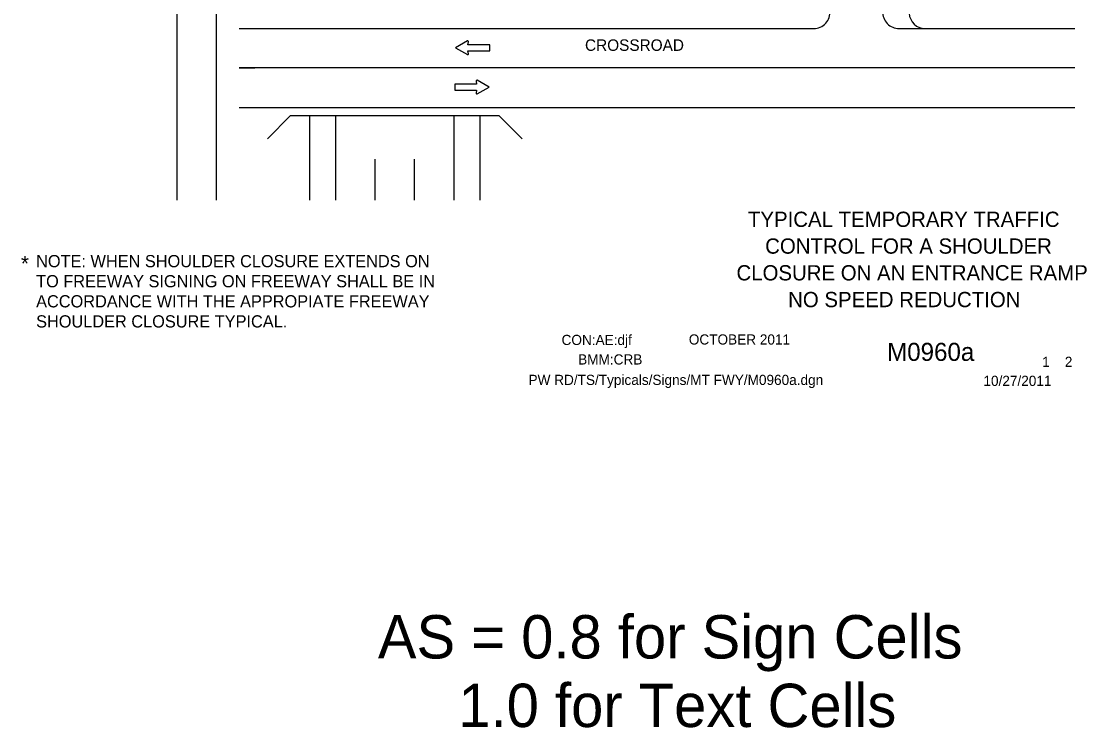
# Model space of a CAD drawing. Extents: x 16733 to 18471, y 4586 to 5876.
# Drawn here: x 16761 to 17411, y 4586 to 5017 of the extents above; entities that cross this region are included whole.
import ezdxf

# ---------------------------------------------------------------- set-up
doc = ezdxf.new("R2010")
doc.units = 0
for name, color, linetype in [('BORDER', 7, 'Continuous'), ('BORDER_SIGNAL_WO', 7, 'Continuous'), ('MT_SCRATCH_LEVEL_E', 7, 'Continuous'), ('PAVT_EDGE_EX', 7, 'Continuous'), ('TRAFFIC_SIGNS_PR', 7, 'Continuous')]:
    doc.layers.add(name, color=color, linetype=linetype)

msp = doc.modelspace()

# ---------------------------------------------------------------- linework, layer by layer
at = {"layer": 'MT_SCRATCH_LEVEL_E'}
for p, q in [((17033.24, 5004.69), (17026, 5000.54)), ((17033.24, 5004.69), (17026, 5000.54)), ((17033.61, 5002.43), (17033.92, 5004.21)), ((17033.61, 5002.43), (17033.92, 5004.21)), ((17046.86, 5002.43), (17033.61, 5002.43)), ((17046.86, 5002.43), (17033.61, 5002.43)), ((17046.86, 4998.69), (17046.86, 5002.43)), ((17046.86, 4998.69), (17046.86, 5002.43)), ((17026, 5000.54), (17033.24, 4996.43)), ((17026, 5000.54), (17033.24, 4996.43)), ((17033.92, 4996.91), (17033.61, 4998.69)), ((17033.61, 4998.69), (17046.86, 4998.69)), ((17033.92, 4996.91), (17033.61, 4998.69)), ((17033.61, 4998.69), (17046.86, 4998.69)), ((17038.89, 4978.47), (17025.63, 4978.47)), ((17025.63, 4978.47), (17025.63, 4974.73)), ((17038.89, 4978.47), (17025.63, 4978.47)), ((17025.63, 4978.47), (17025.63, 4974.73)), ((17038.57, 4980.25), (17038.89, 4978.47)), ((17038.57, 4980.25), (17038.89, 4978.47)), ((17046.5, 4976.62), (17039.26, 4980.73)), ((17046.5, 4976.62), (17039.26, 4980.73)), ((17039.26, 4972.47), (17046.5, 4976.62)), ((17039.26, 4972.47), (17046.5, 4976.62)), ((17025.63, 4974.73), (17038.89, 4974.73)), ((17025.63, 4974.73), (17038.89, 4974.73)), ((17038.89, 4974.73), (17038.57, 4972.95)), ((17038.89, 4974.73), (17038.57, 4972.95))]:
    msp.add_line(p, q, dxfattribs=at)
for centre, start, end in [((17033.46, 5004.28), 350.03619, 119.77312), ((17033.46, 5004.28), 350.03619, 119.77312), ((17033.46, 4996.84), 240.42484, 9.96381), ((17033.46, 4996.84), 240.42484, 9.96381), ((17039.03, 4980.32), 60.42484, 189.96381), ((17039.03, 4980.32), 60.42484, 189.96381), ((17039.03, 4972.88), 170.03619, 299.77312), ((17039.03, 4972.88), 170.03619, 299.77312)]:
    msp.add_arc(centre, 0.463, start, end, dxfattribs=at)
at = {"layer": 'PAVT_EDGE_EX'}
for p, q in [((16894.1, 5012.24), (17244.4, 5012.24)), ((17296.56, 5012.24), (17403.74, 5012.24)), ((16894.1, 4964.24), (17403.74, 4964.24)), ((16925.44, 4959.24), (16911.3, 4945.09)), ((16925.44, 4959.24), (17052.44, 4959.24)), ((16936.94, 4959.24), (16936.94, 4907.7)), ((16952.94, 4959.24), (16952.94, 4907.7)), ((17024.94, 4959.24), (17024.94, 4907.7)), ((17040.94, 4959.24), (17040.94, 4907.7)), ((17052.44, 4959.24), (17066.58, 4945.09))]:
    msp.add_line(p, q, dxfattribs=at)
for centre, radius, start, end in [((17244.4, 5022.24), 10, 270, 4.97638), ((17296.56, 5022.24), 10.03, 177.54481, 270), ((17312.6, 5022.24), 10, 183.82656, 270)]:
    msp.add_arc(centre, radius, start, end, dxfattribs=at)
at = {"layer": 'TRAFFIC_SIGNS_PR'}
for p, q in [((16856.22, 4907.7), (16856.22, 5862.15)), ((16880.22, 4907.7), (16880.22, 5862.15)), ((17403.74, 4988.24), (16894.1, 4988.24))]:
    msp.add_line(p, q, dxfattribs=at)
for points in [[(16894.1, 4988.24), (16903.74, 4988.24)], [(16894.1, 4988.24), (16903.74, 4988.24)], [(17003.74, 4988.24), (16978.74, 4988.24)], [(17103.74, 4988.24), (17078.74, 4988.24)], [(17203.74, 4988.24), (17178.74, 4988.24)], [(17303.74, 4988.24), (17278.74, 4988.24)], [(17403.74, 4988.24), (17378.74, 4988.24)], [(16976.94, 4907.7), (16976.94, 4932.7)], [(17000.94, 4907.7), (17000.94, 4932.7)]]:
    msp.add_lwpolyline(points, dxfattribs=at)

# ---------------------------------------------------------------- texts
at = {"layer": 'BORDER'}
msp.add_text('CROSSROAD', height=7, rotation=360, dxfattribs=at).set_placement((17104.99, 4998.67))
msp.add_text('*', height=9.3, dxfattribs=at).set_placement((16761.06, 4864.43))
at = {"layer": 'BORDER_SIGNAL_WO'}
for s, height, p in [('TYPICAL TEMPORARY TRAFFIC', 9.3, (17204.35, 4891.38)), ('CONTROL FOR A SHOULDER', 9.3, (17214.85, 4875.08)), ('CLOSURE ON AN ENTRANCE RAMP', 9.3, (17197.35, 4858.78)), ('NO SPEED REDUCTION', 9.3, (17228.85, 4842.48)), ('CON:AE:djf  ', 6.2, (17090.69, 4819.43)), ('    OCTOBER 2011    ', 6.2, (17159.08, 4819.71)), ('    M0960a   ', 11, (17272.86, 4809.75)), ('BMM:CRB   ', 6.2, (17100.81, 4807.54)), (' 1    2 ', 6.2, (17381.45, 4806.07)), ('PW RD/TS/Typicals/Signs/MT FWY/M0960a.dgn      ', 6.2, (17070.55, 4795.08)), ('10/27/2011    ', 6.2, (17347.93, 4794.5)), ('AS = 0.8 for Sign Cells', 26.4241, (16978.67, 4628.41)), ('     1.0 for Text Cells', 26.4241, (16978.67, 4586.62))]:
    msp.add_text(s, height=height, dxfattribs=at).set_placement(p)
at = {"layer": 'TRAFFIC_SIGNS_PR'}
for s, p in [('NOTE: WHEN SHOULDER CLOSURE EXTENDS ON', (16770.29, 4866.83)), ('TO FREEWAY SIGNING ON FREEWAY SHALL BE IN', (16770.29, 4854.59)), ('ACCORDANCE WITH THE APPROPIATE FREEWAY', (16770.29, 4842.35)), ('SHOULDER CLOSURE TYPICAL.', (16770.29, 4830.11))]:
    msp.add_text(s, height=7.44, dxfattribs=at).set_placement(p)

doc.saveas('drawing.dxf')
